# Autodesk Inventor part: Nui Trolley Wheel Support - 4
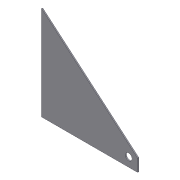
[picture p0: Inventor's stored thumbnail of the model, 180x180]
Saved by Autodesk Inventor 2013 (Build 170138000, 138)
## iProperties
Shininess: 64.0
Length Units: 11269
Angle Units: 11279
Time Units: 11290
Mass Units: 11286
Length Display Precision: 3
Angle Display Precision: 2
Created: 2002-08
Part Number: Nui Trolley Wheel Support - 4
Document SubType Name: Modeling
Designer: kalamea
Density: 1 g/cm^3
Material: Generic
Mass: 129.839 g
Surface Area: 849.404 cm^2
Volume: 129.839 cm^3
Density: 0.0
Volumn: 0.0
Area: 0.0
PropertySet Name: Model Information
Control State: 0
Master: False
Checked Out: False
DRAWING NUMBER: ME03-2007-PT
Author: kalamea
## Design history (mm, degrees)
sketch "Sketch1"
  geometry: L1 (0, 266.7)-(0, 0); L2 (0, 0)-(273.05, 0); L3 (273.05, 0)-(273.05, 34.925); L4 (273.05, 34.925)-(0, 266.7); 1 further point
  constraints: 8 end point, 1 coincident, 1 parallel, 1 perpendicular, 1 vertical
  dimensions: "d0" = 266.7 distance of L1.start L1.end; "d1" = 273.05 distance of L1.end L2.end; "d2" = 34.925 distance of L2.end L3.end
extrude "Extrusion1" new body sketch "Sketch1" stored distance "d3" = 3.175; taper "d4" = 0 deg
sketch "Sketch2"
  geometry: L1 (273.05, 0)-(0, 0) reference; 1 further point
  dimensions: "d5" = 25.4 horizontal distance of L1.start point (247.65, 25.4); "d6" = 25.4 distance from line of point (247.65, 25.4) L1
hole "Hole1" sketch "Sketch2" at (247.65, 25.4) diameter "d7" = 19.05; stored, may be unused: countersink angle "d11" = 82 deg, drill point angle "d13" = 118 deg; dims "d8" = 12.7, "d9" = 9.525, "d10" = 6.35, "d12" = 19.05
body "Solid1"
